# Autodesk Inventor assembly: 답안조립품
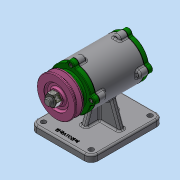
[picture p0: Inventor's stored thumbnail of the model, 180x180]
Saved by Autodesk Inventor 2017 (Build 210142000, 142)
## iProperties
Part Number: 답안조립품
Material: 일반
Document SubType Name: Assembly
Designer: MRC
Author: MRC
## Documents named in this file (12)
- C:\Users\MRC\OneDrive\바탕 화면\720716V1005\답안조립품.iam
- C:\Users\MRC\OneDrive\바탕 화면\720716V1005\본체.ipt
- C:\Users\MRC\OneDrive\바탕 화면\720716V1005\V-벨트풀리.ipt
- C:\Users\MRC\OneDrive\바탕 화면\720716V1005\개스킷.ipt
- C:\Users\MRC\OneDrive\바탕 화면\720716V1005\너트 M12 x 1.25.ipt
- C:\Users\MRC\OneDrive\바탕 화면\720716V1005\뒤커버.ipt
- C:\Users\MRC\OneDrive\바탕 화면\720716V1005\베어링 6204.ipt
- C:\Users\MRC\OneDrive\바탕 화면\720716V1005\볼트 M4 x 12.ipt
- C:\Users\MRC\OneDrive\바탕 화면\720716V1005\앞커버.ipt
- C:\Users\MRC\OneDrive\바탕 화면\720716V1005\오일 실.ipt
- C:\Users\MRC\OneDrive\바탕 화면\720716V1005\축.ipt
- C:\Users\MRC\OneDrive\바탕 화면\720716V1005\키 4 x 4.ipt
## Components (3 placed, 2 different names)
1. V-벨트풀리:1
2. 개스킷:1
3. 개스킷:2
